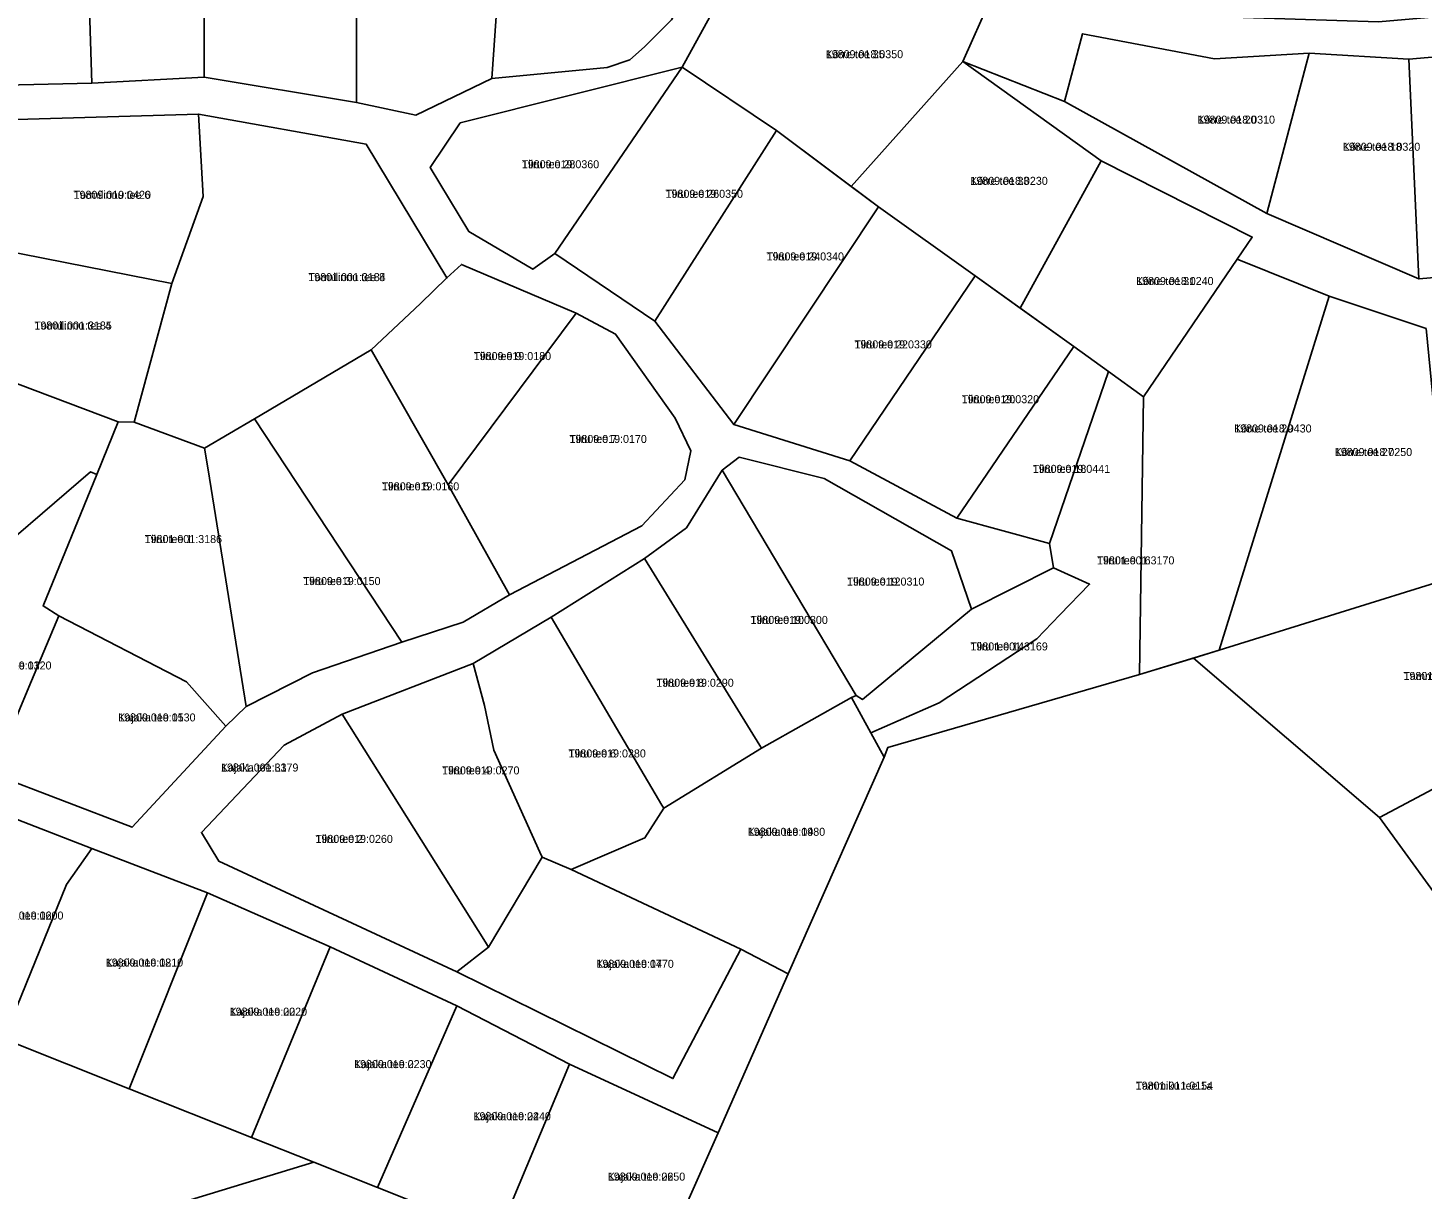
# Model space of a CAD drawing. Extents: x 516875 to 535633, y 6574491 to 6593094.
# Drawn here: x 520561.2 to 520822.5, y 6588801.2 to 6589018.9 of the extents above; entities that cross this region are included whole.
import ezdxf

# ---------------------------------------------------------------- set-up
doc = ezdxf.new("R2010")
doc.units = 0
for name, color, linetype in [('L_AADRESS', 7, 'Continuous'), ('PIIR', 7, 'Continuous'), ('TUNNUS', 7, 'Continuous')]:
    doc.layers.add(name, color=color, linetype=linetype)

msp = doc.modelspace()

# ---------------------------------------------------------------- linework, layer by layer
at = {"layer": 'PIIR'}
for points in [[(520557.48, 6589065.33), (520571.46, 6589064.22), (520571.79, 6589053.84), (520573.19, 6589008.55), (520548.68, 6589007.97), (520547.78, 6589048.63), (520544.83, 6589049.11), (520545.34, 6589055.86), (520546.15, 6589066.23)], [(520571.79, 6589053.84), (520571.46, 6589064.22), (520594.31, 6589062.39), (520594.31, 6589055.13), (520594.26, 6589009.66), (520573.19, 6589008.55)], [(520594.31, 6589055.13), (520594.31, 6589062.39), (520607.21, 6589061.36), (520617.77, 6589060.53), (520617.79, 6589055.75), (520622.82, 6589041.98), (520622.82, 6589004.93), (520594.26, 6589009.66)], [(520622.82, 6589041.98), (520617.79, 6589055.75), (520617.77, 6589060.53), (520651.62, 6589057.83), (520651.25, 6589053.32), (520648.14, 6589009.41), (520633.95, 6589002.57), (520622.82, 6589004.93)], [(520665.44, 6589056.65), (520690.68, 6589042.54), (520683.58, 6589027.81), (520685.17, 6589027.02), (520681.82, 6589020.4), (520676.78, 6589015.39), (520674, 6589012.93), (520669.79, 6589011.47), (520648.14, 6589009.41), (520651.25, 6589053.32), (520651.62, 6589057.83), (520652.35, 6589057.76)], [(520741.58, 6589024.28), (520729.33, 6589027.15), (520697.96, 6589037.27), (520702.1, 6589045.03), (520742.8, 6589030.91), (520749, 6589028.92), (520783.08, 6589021.07), (520814.31, 6589020.02), (520856.6, 6589023.71), (520856.94, 6589021.08), (520880.58, 6589027.59), (520880.36, 6589030.08), (520906.95, 6589040.68), (520905.42, 6589030.81), (520853.02, 6589015.9), (520838.83, 6589014.66), (520820.01, 6589013.02), (520801.33, 6589014.17), (520783.59, 6589013.09), (520758.83, 6589017.81), (520755.49, 6589005.12), (520736.42, 6589012.59)], [(520697.96, 6589037.27), (520729.33, 6589027.15), (520741.58, 6589024.28), (520736.42, 6589012.59), (520715.51, 6588989.19), (520701.48, 6588999.67), (520683.81, 6589011.52)], [(520758.83, 6589017.81), (520783.59, 6589013.09), (520801.33, 6589014.17), (520793.37, 6588984.1), (520755.49, 6589005.12)], [(520801.33, 6589014.17), (520820.01, 6589013.02), (520821.89, 6588971.86), (520793.37, 6588984.1)], [(520820.01, 6589013.02), (520838.83, 6589014.66), (520845.4, 6588973.88), (520821.89, 6588971.86)], [(520683.81, 6589011.52), (520659.96, 6588976.61), (520655.84, 6588973.68), (520643.85, 6588980.73), (520636.58, 6588992.76), (520642.26, 6589001.12)], [(520683.81, 6589011.52), (520701.48, 6588999.67), (520678.69, 6588963.94), (520659.96, 6588976.61)], [(520762.34, 6588993.98), (520747.15, 6588966.4), (520738.71, 6588972.43), (520720.62, 6588985.37), (520715.51, 6588989.19), (520736.42, 6589012.59)], [(520547.1, 6588993.42), (520549.15, 6588997.25), (520556.96, 6589001.69), (520593.18, 6589002.76), (520594.1, 6588987.31), (520588.23, 6588970.97), (520544.03, 6588979.71)], [(520594.1, 6588987.31), (520593.18, 6589002.76), (520624.64, 6588997.1), (520639.74, 6588972.03), (520634.82, 6588967.23), (520625.54, 6588958.58), (520603.67, 6588945.63), (520594.33, 6588940.12), (520581.17, 6588945.03), (520588.23, 6588970.97)], [(520701.48, 6588999.67), (520720.62, 6588985.37), (520693.51, 6588944.59), (520678.69, 6588963.94)], [(520747.15, 6588966.4), (520762.34, 6588993.98), (520790.66, 6588979.69), (520787.85, 6588975.55), (520770.29, 6588949.76), (520763.72, 6588954.47), (520757.21, 6588959.21)], [(520720.62, 6588985.37), (520738.71, 6588972.43), (520715.22, 6588937.77), (520693.51, 6588944.59)], [(520553.11, 6588954.48), (520538.32, 6588959.99), (520544.03, 6588979.71), (520588.23, 6588970.97), (520581.17, 6588945.03), (520578.16, 6588945.06)], [(520634.82, 6588967.23), (520639.74, 6588972.03), (520642.48, 6588974.58), (520663.99, 6588965.41), (520639.96, 6588933.25), (520625.54, 6588958.58)], [(520787.85, 6588975.55), (520805.04, 6588968.64), (520784.43, 6588902.27), (520769.51, 6588897.67), (520770.29, 6588949.76)], [(520738.71, 6588972.43), (520757.21, 6588959.21), (520735.31, 6588927.03), (520715.22, 6588937.77)], [(520823.25, 6588962.53), (520827.78, 6588915.75), (520784.43, 6588902.27), (520805.04, 6588968.64)], [(520663.99, 6588965.41), (520671.34, 6588961.51), (520682.55, 6588945.72), (520685.47, 6588939.6), (520684.31, 6588934.17), (520676.26, 6588925.55), (520651.45, 6588912.64), (520639.96, 6588933.25)], [(520625.54, 6588958.58), (520639.96, 6588933.25), (520651.45, 6588912.64), (520642.81, 6588907.51), (520631.3, 6588903.73), (520603.67, 6588945.63)], [(520757.21, 6588959.21), (520763.72, 6588954.47), (520752.67, 6588922.23), (520735.31, 6588927.03)], [(520541.23, 6588919.15), (520505.11, 6588932.2), (520511.92, 6588945.41), (520532.78, 6588954.93), (520550.14, 6588946.57), (520553.11, 6588954.48), (520578.16, 6588945.06), (520574.18, 6588935.22), (520572.99, 6588935.67), (520549.97, 6588915.97)], [(520760.16, 6588914.61), (520753.41, 6588917.67), (520752.67, 6588922.23), (520763.72, 6588954.47), (520770.29, 6588949.76), (520769.51, 6588897.67), (520722.36, 6588884), (520721.67, 6588882.21), (520719.17, 6588886.74), (520731.98, 6588892.4), (520750.29, 6588904.37), (520754.58, 6588908.89)], [(520595.04, 6588936.09), (520602.13, 6588891.7), (520598.34, 6588888.03), (520590.93, 6588896.33), (520567.01, 6588908.72), (520564.09, 6588910.55), (520574.18, 6588935.22), (520578.16, 6588945.06), (520581.17, 6588945.03), (520594.33, 6588940.12)], [(520595.04, 6588936.09), (520594.33, 6588940.12), (520603.67, 6588945.63), (520631.3, 6588903.73), (520614.56, 6588898.04), (520602.13, 6588891.7)], [(520717.62, 6588893.03), (520716.45, 6588893.77), (520691.35, 6588935.98), (520694.5, 6588938.45), (520710.44, 6588934.45), (520734.28, 6588920.91), (520738.06, 6588909.94)], [(520564.09, 6588910.55), (520567.01, 6588908.72), (520561.43, 6588895.3), (520554.59, 6588879.1), (520528.14, 6588888.24), (520541.23, 6588919.15), (520549.97, 6588915.97), (520572.99, 6588935.67), (520574.18, 6588935.22)], [(520716.45, 6588893.77), (520715.55, 6588893.36), (520698.69, 6588883.88), (520698.37, 6588884.39), (520676.78, 6588919.45), (520684.63, 6588925.18), (520691.35, 6588935.98)], [(520784.43, 6588902.27), (520827.78, 6588915.75), (520849.24, 6588922.42), (520854.33, 6588892.08), (520842.48, 6588885.78), (520814.52, 6588870.91), (520779.62, 6588900.77)], [(520698.37, 6588884.39), (520698.69, 6588883.88), (520680.38, 6588872.64), (520680.01, 6588873.2), (520659.29, 6588908.42), (520676.78, 6588919.45)], [(520738.06, 6588909.94), (520753.41, 6588917.67), (520760.16, 6588914.61), (520754.58, 6588908.89), (520750.29, 6588904.37), (520731.98, 6588892.4), (520719.17, 6588886.74), (520715.55, 6588893.36), (520716.45, 6588893.77), (520717.62, 6588893.03)], [(520590.93, 6588896.33), (520598.34, 6588888.03), (520580.8, 6588869.07), (520554.59, 6588879.1), (520561.43, 6588895.3), (520567.01, 6588908.72)], [(520680.01, 6588873.2), (520680.38, 6588872.64), (520676.86, 6588867.09), (520663.02, 6588861.15), (520657.58, 6588863.47), (520657.17, 6588864.37), (520648.57, 6588883.52), (520646.8, 6588891.89), (520644.65, 6588899.73), (520659.29, 6588908.42)], [(520769.51, 6588897.67), (520779.62, 6588900.77), (520814.52, 6588870.91), (520839.55, 6588836.4), (520845.25, 6588812.63), (520842.85, 6588790.6), (520838.33, 6588749.48), (520874.94, 6588741.54), (520872.74, 6588738.96), (520831.43, 6588747.99), (520808.6, 6588752.98), (520786.44, 6588757.82), (520762.68, 6588763.01), (520739.61, 6588768.06), (520713.78, 6588773.7), (520678.93, 6588781.32), (520677.03, 6588781.59), (520677.94, 6588783.37), (520690.55, 6588811.8), (520703.68, 6588841.57), (520721.67, 6588882.21), (520722.36, 6588884)], [(520646.8, 6588891.89), (520648.57, 6588883.52), (520657.17, 6588864.37), (520657.58, 6588863.47), (520647.57, 6588846.57), (520646.99, 6588847.49), (520620.11, 6588890.27), (520644.65, 6588899.73)], [(520694.8, 6588846.18), (520663.02, 6588861.15), (520676.86, 6588867.09), (520680.38, 6588872.64), (520698.69, 6588883.88), (520715.55, 6588893.36), (520719.17, 6588886.74), (520721.67, 6588882.21), (520703.68, 6588841.57)], [(520593.74, 6588868.1), (520609.27, 6588884.48), (520620.11, 6588890.27), (520646.99, 6588847.49), (520647.57, 6588846.57), (520641.61, 6588841.99), (520597.04, 6588862.7)], [(520842.48, 6588885.78), (520897.63, 6588865.53), (520839.55, 6588836.4), (520814.52, 6588870.91)], [(520548.57, 6588874.67), (520573.22, 6588865.1), (520568.46, 6588858.34), (520556.75, 6588829.39), (520533.57, 6588838.63)], [(520568.46, 6588858.34), (520573.22, 6588865.1), (520594.88, 6588856.76), (520580.19, 6588820.05), (520556.75, 6588829.39)], [(520647.57, 6588846.57), (520657.58, 6588863.47), (520663.02, 6588861.15), (520694.8, 6588846.18), (520682.09, 6588821.95), (520641.61, 6588841.99)], [(520594.88, 6588856.76), (520617.88, 6588846.67), (520603.13, 6588810.91), (520580.19, 6588820.05)], [(520510.03, 6588848.01), (520533.57, 6588838.63), (520556.75, 6588829.39), (520580.19, 6588820.05), (520603.13, 6588810.91), (520614.8, 6588806.25), (520491.67, 6588768.67), (520485.64, 6588771.35), (520459.44, 6588806.46), (520489.64, 6588819.09), (520491.78, 6588820.65), (520506.06, 6588851.77)], [(520617.88, 6588846.67), (520641.59, 6588835.59), (520626.74, 6588801.5), (520614.8, 6588806.25), (520603.13, 6588810.91)], [(520641.59, 6588835.59), (520662.73, 6588824.67), (520649.26, 6588792.52), (520626.74, 6588801.5)], [(520662.73, 6588824.67), (520690.55, 6588811.8), (520677.94, 6588783.37), (520677.03, 6588781.59), (520675.13, 6588782.21), (520649.26, 6588792.52)]]:
    msp.add_lwpolyline(points, close=True, dxfattribs=at)
for points in [[(520697.96, 6589037.27), (520683.81, 6589011.52), (520642.26, 6589001.12), (520636.58, 6588992.76), (520643.85, 6588980.73), (520655.84, 6588973.68), (520659.96, 6588976.61), (520678.69, 6588963.94), (520693.51, 6588944.59), (520715.22, 6588937.77), (520735.31, 6588927.03), (520752.67, 6588922.23), (520753.41, 6588917.67), (520738.06, 6588909.94), (520734.28, 6588920.91), (520710.44, 6588934.45), (520694.5, 6588938.45), (520691.35, 6588935.98), (520684.63, 6588925.18), (520676.78, 6588919.45), (520659.29, 6588908.42), (520644.65, 6588899.73), (520620.11, 6588890.27), (520609.27, 6588884.48), (520593.74, 6588868.1), (520597.04, 6588862.7), (520641.61, 6588841.99), (520682.09, 6588821.95), (520694.8, 6588846.18), (520703.68, 6588841.57), (520690.55, 6588811.8), (520662.73, 6588824.67), (520641.59, 6588835.59), (520617.88, 6588846.67), (520594.88, 6588856.76), (520573.22, 6588865.1), (520548.57, 6588874.67)], [(520548.68, 6589007.97), (520573.19, 6589008.55), (520594.26, 6589009.66), (520622.82, 6589004.93), (520633.95, 6589002.57), (520648.14, 6589009.41), (520669.79, 6589011.47), (520674, 6589012.93), (520676.78, 6589015.39), (520681.82, 6589020.4)], [(520823.25, 6588962.53), (520805.04, 6588968.64), (520787.85, 6588975.55), (520790.66, 6588979.69), (520762.34, 6588993.98), (520736.42, 6589012.59), (520755.49, 6589005.12), (520793.37, 6588984.1), (520821.89, 6588971.86), (520845.4, 6588973.88)], [(520554.59, 6588879.1), (520580.8, 6588869.07), (520598.34, 6588888.03), (520602.13, 6588891.7), (520614.56, 6588898.04), (520631.3, 6588903.73), (520642.81, 6588907.51), (520651.45, 6588912.64), (520676.26, 6588925.55), (520684.31, 6588934.17), (520685.47, 6588939.6), (520682.55, 6588945.72), (520671.34, 6588961.51), (520663.99, 6588965.41), (520642.48, 6588974.58), (520639.74, 6588972.03), (520624.64, 6588997.1), (520593.18, 6589002.76), (520556.96, 6589001.69)], [(520491.67, 6588768.67), (520614.8, 6588806.25), (520626.74, 6588801.5), (520649.26, 6588792.52), (520675.13, 6588782.21), (520677.03, 6588781.59), (520676.39, 6588779.83), (520666.74, 6588748.27), (520654.56, 6588711.89), (520625.31, 6588628.59), (520618.23, 6588615.82), (520612.63, 6588617.78), (520609.68, 6588609.45), (520614.48, 6588607.78), (520609.92, 6588597.61), (520635.14, 6588588.4), (520632.9, 6588567.13), (520563.49, 6588569.56), (520558.05, 6588569.21)]]:
    msp.add_lwpolyline(points, dxfattribs=at)

# ---------------------------------------------------------------- texts
at = {"layer": 'L_AADRESS'}
for s, p in [('Kõrre tee 35', (520710.73, 6589013.23)), ('Kõrre tee 20', (520780.41, 6589000.96)), ('Kõrre tee 18', (520807.63, 6588995.88)), ('Tiiru tee 28', (520653.78, 6588992.6)), ('Kõrre tee 33', (520737.83, 6588989.49)), ('Tormilinnu tee 6', (520569.79, 6588986.87)), ('Tiiru tee 26', (520680.72, 6588987.06)), ('Tiiru tee 24', (520699.65, 6588975.32)), ('Tormilinnu tee 8', (520613.77, 6588971.44)), ('Kõrre tee 31', (520768.9, 6588970.71)), ('Tormilinnu tee 4', (520562.45, 6588962.37)), ('Tiiru tee 9', (520644.77, 6588956.64)), ('Tiiru tee 22', (520716.11, 6588958.83)), ('Tiiru tee 20', (520736.21, 6588948.55)), ('Tiiru tee 7', (520662.71, 6588941.1)), ('Kõrre tee 29', (520787.27, 6588943.07)), ('Kõrre tee 27', (520806.11, 6588938.65)), ('Tiiru tee 18', (520749.52, 6588935.5)), ('Tiiru tee 5', (520627.56, 6588932.22)), ('Tiiru tee 1', (520583.11, 6588922.34)), ('Tiiru tee 16', (520761.56, 6588918.34)), ('Tiiru tee 3', (520612.81, 6588914.46)), ('Tiiru tee 12', (520714.71, 6588914.37)), ('Tiiru tee 10', (520696.62, 6588907.18)), ('Tiiru tee 14', (520737.84, 6588902.21)), ('Kajaka tee 13', (520551.16, 6588898.64)), ('Tammiku tee 6', (520818.99, 6588896.67)), ('Tiiru tee 8', (520678.99, 6588895.4)), ('Kajaka tee 15', (520578.15, 6588888.9)), ('Tiiru tee 6', (520662.52, 6588882.15)), ('Kajaka tee L3', (520597.42, 6588879.51)), ('Tiiru tee 4', (520638.84, 6588878.97)), ('Kajaka tee 19', (520696.12, 6588867.46)), ('Tiiru tee 2', (520615.11, 6588866.13)), ('Kajaka tee 16', (520553.39, 6588851.76)), ('Kajaka tee 18', (520575.82, 6588842.95)), ('Kajaka tee 17', (520667.76, 6588842.71)), ('Kajaka tee 20', (520599.04, 6588833.74)), ('Kajaka tee 22', (520622.36, 6588823.91)), ('Tammiku tee 1a', (520768.81, 6588819.87)), ('Kajaka tee 24', (520644.73, 6588814.14)), ('Kajaka tee 26', (520669.9, 6588802.82))]:
    msp.add_text(s, height=1.5, dxfattribs=at).set_placement(p)
at = {"layer": 'TUNNUS'}
for s, p in [('19809:018:0350', (520710.73, 6589013.23)), ('19809:018:0310', (520780.41, 6589000.96)), ('19809:018:0320', (520807.63, 6588995.88)), ('19809:019:0360', (520653.78, 6588992.6)), ('19809:018:0230', (520737.83, 6588989.49)), ('19809:019:0420', (520569.79, 6588986.87)), ('19809:019:0350', (520680.72, 6588987.06)), ('19809:019:0340', (520699.65, 6588975.32)), ('19801:001:3184', (520613.77, 6588971.44)), ('19809:018:0240', (520768.9, 6588970.71)), ('19801:001:3185', (520562.45, 6588962.37)), ('19809:019:0180', (520644.77, 6588956.64)), ('19809:019:0330', (520716.11, 6588958.83)), ('19809:019:0320', (520736.21, 6588948.55)), ('19809:019:0170', (520662.71, 6588941.1)), ('19809:018:0430', (520787.27, 6588943.07)), ('19809:018:0250', (520806.11, 6588938.65)), ('19809:019:0441', (520749.52, 6588935.5)), ('19809:019:0160', (520627.56, 6588932.22)), ('19801:001:3186', (520583.11, 6588922.34)), ('19801:001:3170', (520761.56, 6588918.34)), ('19809:019:0150', (520612.81, 6588914.46)), ('19809:019:0310', (520714.71, 6588914.37)), ('19809:019:0300', (520696.62, 6588907.18)), ('19801:001:3169', (520737.84, 6588902.21)), ('19809:019:0120', (520551.16, 6588898.64)), ('19801:011:0159', (520818.99, 6588896.67)), ('19809:019:0290', (520678.99, 6588895.4)), ('19809:019:0130', (520578.15, 6588888.9)), ('19809:019:0280', (520662.52, 6588882.15)), ('19801:001:3179', (520597.42, 6588879.51)), ('19809:019:0270', (520638.84, 6588878.97)), ('19809:019:0480', (520696.12, 6588867.46)), ('19809:019:0260', (520615.11, 6588866.13)), ('19809:019:0200', (520553.39, 6588851.76)), ('19809:019:0210', (520575.82, 6588842.95)), ('19809:019:0470', (520667.76, 6588842.71)), ('19809:019:0220', (520599.04, 6588833.74)), ('19809:019:0230', (520622.36, 6588823.91)), ('19801:011:0154', (520768.81, 6588819.87)), ('19809:019:0240', (520644.73, 6588814.14)), ('19809:019:0250', (520669.9, 6588802.82))]:
    msp.add_text(s, height=1.5, dxfattribs=at).set_placement(p)

doc.saveas('drawing.dxf')
